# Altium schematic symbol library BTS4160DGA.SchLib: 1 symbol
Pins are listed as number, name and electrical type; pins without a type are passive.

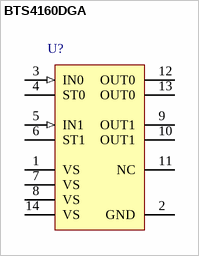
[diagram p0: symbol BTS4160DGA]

## BTS4160DGA
designator U?
Smart High-Side Power Switch, 2 Channels, 1.7 A Load Current, -40 to 150 degC, PG-DSO-14-37, Reel, Green; Manufacturer: Infineon; PartNumber: BTS4160DGA; Channels: 2; Green: TRUE; Group: Automotive Qualified; Load Current (typ): 1.7 A; Ptot (max): 1.4 W; Recommended Operating Voltage Max.: 20 V; Recommended Operating Voltage Min.: 5.5 V; RON @ 25degreesC: 160 mOhm; RON(max) @ 150degreesC: 320 mOhm; toff (max): 270 us; ton (max): 250 us
footprint INF-PG-DSO-14-37_N (SOP, 14-Leads, Body 8.65x3.9mm, Pitch 1.27mm, IPC Medium Density)
footprint INF-PG-DSO-14-37_L (SOP, 14-Leads, Body 8.65x3.9mm, Pitch 1.27mm, IPC High Density)
footprint INF-PG-DSO-14-37_M (SOP, 14-Leads, Body 8.65x3.9mm, Pitch 1.27mm, IPC Low Density)
pins: 1 VS (power) "Battery voltage Design the wiring for the simultaneous max. short circuit currents from channel 0 and 1 and also for low thermal resistance", 2 GND (power) "Ground; Ground connection", 3 IN0 (in) "Input channel 0; Input signal for channel 0. Activate the channel in case of logic high level", 4 ST0 (oc) "Diagnostic feedback; Channel 0. Open drain", 5 IN1 (in) "Input channel 1; Input signal for channel 1. Activate the channel in case of logic high level", 6 ST1 (oc) "Diagnostic feedback; Channel 1. Open drain", 7 VS (power) "Battery voltage Design the wiring for the simultaneous max. short circuit currents from channel 0 and 1 and also for low thermal resistance", 8 VS (power) "Battery voltage Design the wiring for the simultaneous max. short circuit currents from channel 0 and 1 and also for low thermal resistance", 9 OUT1 (power) "Output 1; Protected High side power output channel 1", 10 OUT1 (power) "Output 1; Protected High side power output channel 1", 11 NC "Not Connected", 12 OUT0 (power) "Output 0; Protected High side power output channel 0", 13 OUT0 (power) "Output 0; Protected High side power output channel 0", 14 VS (power) "Battery voltage Design the wiring for the simultaneous max. short circuit currents from channel 0 and 1 and also for low thermal resistance"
